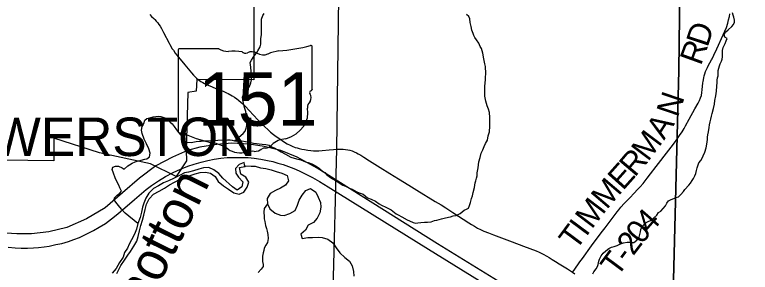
# Model space of a CAD drawing. Extents: x -19.9 to 41.9, y 0 to 32.3.
# Drawn here: x 6.268 to 8.077, y 16.956 to 17.59 of the extents above; entities that cross this region are included whole.
import ezdxf

# ---------------------------------------------------------------- set-up
doc = ezdxf.new("R2010")
doc.units = 0
for name, color, linetype in [('GM_X_Corporation', 7, 'Continuous'), ('GM_X_Corporation_Text', 7, 'Continuous'), ('GM_X_Major_River', 7, 'Continuous'), ('GM_X_Major_River_Text', 7, 'Continuous'), ('GM_X_Minor_River', 7, 'Continuous'), ('GM_X_Rail_Line', 7, 'Continuous'), ('GM_X_State_Location', 7, 'Continuous'), ('GM_X_State_Route', 7, 'Continuous'), ('GM_X_State_Shield', 7, 'Continuous'), ('GM_X_Township', 7, 'Continuous'), ('GM_X_Township_Road', 7, 'Continuous'), ('GM_X_Township_Road_Text', 7, 'Continuous')]:
    doc.layers.add(name, color=color, linetype=linetype)

msp = doc.modelspace()

# ---------------------------------------------------------------- linework, layer by layer
at = {"layer": 'GM_X_Corporation'}
for points in [[(2.1, 17.918), (2.1, 14.1), (7.8246, 14.1), (7.8518, 15.3043), (7.854, 15.4058), (7.8702, 16.1679), (7.8776, 16.5173), (7.9012, 17.4524), (7.9072, 17.9171)], [(6.8558, 17.6308), (6.8557, 17.4298), (6.7153, 17.4299), (6.7144, 17.4018), (6.6932, 17.3984), (6.6898, 17.2551), (6.6899, 17.2302), (6.6652, 17.1916), (6.6019, 17.2222), (6.4766, 17.2495), (6.3638, 17.2855), (6.3638, 17.2303), (5.8542, 17.2364), (5.8562, 17.5075), (6.2079, 17.7506)]]:
    msp.add_lwpolyline(points, dxfattribs=at)
msp.add_lwpolyline([(7.8246, 14.1), (8.9, 14.1), (8.9, 17.8974), (7.9072, 17.9171), (7.9012, 17.4524), (7.8776, 16.5173), (7.8702, 16.1679), (7.854, 15.4058), (7.8518, 15.3043)], close=True, dxfattribs=at)
at = {"layer": 'GM_X_Major_River'}
for points in [[(6.8336, 17.216), (6.8324, 17.2259), (6.8195, 17.2212), (6.8106, 17.2115), (6.8117, 17.2), (6.8184, 17.1897), (6.8291, 17.1784), (6.8263, 17.1658), (6.815, 17.1574), (6.8031, 17.1659), (6.7793, 17.1877), (6.7697, 17.1989), (6.7574, 17.2079), (6.7448, 17.2138), (6.7319, 17.2129), (6.7202, 17.2097), (6.7073, 17.2054), (6.6952, 17.2018), (6.6853, 17.2002), (6.6729, 17.194), (6.6601, 17.1874), (6.6457, 17.1804), (6.634, 17.1757), (6.6215, 17.1687), (6.6087, 17.1621), (6.5975, 17.1506), (6.5904, 17.1383), (6.5856, 17.1257), (6.5819, 17.1162), (6.5794, 17.1037), (6.5762, 17.0907), (6.5706, 17.0755), (6.5674, 17.0618), (6.5626, 17.0492), (6.5552, 17.0358), (6.5496, 17.0251), (6.5448, 17.0152), (6.5381, 17.0045), (6.5341, 16.9927), (6.5255, 16.9793), (6.5173, 16.9652), (6.5076, 16.9533)], [(6.5186, 16.9527), (6.5242, 16.9626), (6.5286, 16.9721), (6.5376, 16.9855), (6.5461, 16.9974), (6.5525, 17.007), (6.5607, 17.0196), (6.5678, 17.0322), (6.571, 17.044), (6.575, 17.0577), (6.5779, 17.0706), (6.5819, 17.0843), (6.5856, 17.0965), (6.5888, 17.1098), (6.5921, 17.1235), (6.5988, 17.1365), (6.6089, 17.1477), (6.6232, 17.155), (6.6361, 17.1624), (6.6481, 17.1705), (6.6606, 17.1771), (6.6745, 17.1849), (6.6862, 17.1903), (6.6991, 17.1939), (6.7119, 17.1982), (6.7237, 17.2014), (6.737, 17.202), (6.7491, 17.1998), (6.7606, 17.1912), (6.7684, 17.1788), (6.781, 17.1683), (6.7937, 17.1605), (6.8067, 17.1516), (6.8196, 17.1483), (6.831, 17.153), (6.8392, 17.1649), (6.8436, 17.1778), (6.8362, 17.1895), (6.8236, 17.1969), (6.8203, 17.2132)], [(6.8203, 17.2132), (6.8336, 17.216)], [(6.8336, 17.216), (6.8363, 17.2176), (6.8492, 17.217), (6.8594, 17.2167), (6.8724, 17.2127), (6.8857, 17.2113), (6.8987, 17.2077), (6.9105, 17.2037), (6.9246, 17.1993), (6.9376, 17.1938), (6.9415, 17.1805), (6.934, 17.1698), (6.9216, 17.1625), (6.9088, 17.1566), (6.8963, 17.1496), (6.8885, 17.137), (6.8898, 17.1245), (6.8956, 17.112), (6.9083, 17.1008), (6.9213, 17.096), (6.9308, 17.0954), (6.9444, 17.1005), (6.9576, 17.1079), (6.9631, 17.1208), (6.9671, 17.1334), (6.9746, 17.1456), (6.9836, 17.1567), (6.9957, 17.1615), (7.0083, 17.1525), (7.0141, 17.1404), (7.02, 17.1276), (7.0205, 17.1158), (7.018, 17.1021), (7.0113, 17.0892), (7.0024, 17.0784), (6.9895, 17.0718), (6.9832, 17.0592), (6.9712, 17.0496), (6.9747, 17.039), (6.9884, 17.0414), (7.0001, 17.0416), (7.0138, 17.0421), (7.0237, 17.0415), (7.0378, 17.0371), (7.0504, 17.0282), (7.0582, 17.0161), (7.0678, 17.0037), (7.0797, 16.9917), (7.0916, 16.9827), (7.0982, 16.9711), (7.1014, 16.9578), (7.1023, 16.9457)]]:
    msp.add_lwpolyline(points, dxfattribs=at)
at = {"layer": 'GM_X_Minor_River'}
for points in [[(6.8082, 17.2791), (6.8295, 17.297), (6.8344, 17.3031), (6.8369, 17.31), (6.8383, 17.3169), (6.8381, 17.3348), (6.8372, 17.3458), (6.8363, 17.3512), (6.8347, 17.3561), (6.8332, 17.3614), (6.8304, 17.372), (6.8287, 17.3811), (6.8282, 17.3868), (6.8304, 17.3922), (6.8338, 17.3972), (6.8416, 17.408), (6.8453, 17.413), (6.8486, 17.4218), (6.8504, 17.4298), (6.851, 17.4397), (6.8497, 17.45), (6.8484, 17.4607), (6.8476, 17.466), (6.8471, 17.4724), (6.8501, 17.4778), (6.8545, 17.484), (6.8575, 17.489), (6.8623, 17.4948), (6.866, 17.5009), (6.8715, 17.5105), (6.8734, 17.517), (6.8732, 17.5254), (6.8735, 17.5304), (6.8745, 17.541), (6.8744, 17.5468), (6.875, 17.5616), (6.8748, 17.5723), (6.8751, 17.5791), (6.8777, 17.5876), (6.881, 17.5929)], [(7.0412, 17.1912), (7.0496, 17.1853), (7.0606, 17.179), (7.0751, 17.1704), (7.0812, 17.1675), (7.0927, 17.1619), (7.0976, 17.1601), (7.1091, 17.1534), (7.1148, 17.1512), (7.1251, 17.1476), (7.1354, 17.139), (7.1442, 17.136), (7.1548, 17.1305), (7.1644, 17.1245), (7.1701, 17.1212), (7.1804, 17.116), (7.1934, 17.109), (7.206, 17.0993), (7.2113, 17.0971), (7.2201, 17.0919), (7.2327, 17.0848), (7.2392, 17.0826), (7.2476, 17.0782), (7.2537, 17.0768), (7.259, 17.0776), (7.2665, 17.0785), (7.276, 17.079), (7.2835, 17.0791), (7.2922, 17.08), (7.3005, 17.0828), (7.3062, 17.084), (7.3179, 17.0873), (7.3239, 17.0885), (7.3349, 17.0917), (7.3401, 17.0925), (7.3465, 17.0945), (7.3534, 17.095), (7.3582, 17.0978), (7.3635, 17.1005), (7.3732, 17.1087), (7.3789, 17.1114), (7.3838, 17.1134), (7.3867, 17.1203), (7.3889, 17.1272), (7.3917, 17.1375), (7.3935, 17.1436), (7.3953, 17.1524), (7.3986, 17.1643), (7.4007, 17.1761), (7.4017, 17.1811), (7.4035, 17.1872), (7.405, 17.1933), (7.4056, 17.2002), (7.4077, 17.2128), (7.4098, 17.2273), (7.4123, 17.238), (7.4151, 17.2491), (7.4192, 17.2567), (7.4225, 17.2656), (7.4262, 17.2725), (7.4306, 17.2805), (7.4323, 17.2912), (7.4356, 17.3012), (7.4362, 17.3153), (7.4364, 17.324), (7.4366, 17.337), (7.4353, 17.3492), (7.4329, 17.3575), (7.4302, 17.3651), (7.427, 17.3765), (7.4245, 17.3894), (7.4239, 17.4042), (7.4245, 17.4141), (7.4258, 17.4298), (7.4263, 17.4511), (7.4262, 17.4564), (7.4254, 17.4621), (7.4241, 17.469), (7.4221, 17.4811), (7.4192, 17.4948), (7.4157, 17.5069), (7.4129, 17.5118), (7.409, 17.5194), (7.4036, 17.5281), (7.3998, 17.5334), (7.397, 17.5383), (7.3958, 17.5432), (7.3923, 17.5519), (7.3903, 17.561), (7.3883, 17.5709), (7.387, 17.5793), (7.3846, 17.5849), (7.3793, 17.5902)], [(7.9685, 17.2617), (7.9706, 17.2708), (7.9716, 17.2823), (7.9719, 17.288), (7.973, 17.2937), (7.9744, 17.3017), (7.9761, 17.3124), (7.9771, 17.3185), (7.9786, 17.3262), (7.9804, 17.3327), (7.9818, 17.3399), (7.9832, 17.3464), (7.9864, 17.359), (7.9889, 17.3698), (7.9903, 17.3785), (7.992, 17.3896), (7.9938, 17.4018), (7.9947, 17.414), (7.9954, 17.4232), (7.9953, 17.4289), (7.9963, 17.4342), (7.9981, 17.4396), (7.9984, 17.4476), (7.9983, 17.4525), (7.9994, 17.4579), (8.0012, 17.4636), (8.0027, 17.4686), (8.006, 17.4755), (8.0078, 17.4805), (8.0089, 17.4862), (8.0086, 17.5015), (8.0108, 17.5087), (8.0152, 17.5191), (8.0178, 17.5256), (8.02, 17.531), (8.0146, 17.5347), (8.0126, 17.5404), (8.0163, 17.5465), (8.0231, 17.5527), (8.0317, 17.5605), (8.0361, 17.5655), (8.0383, 17.5712), (8.0383, 17.5762), (8.037, 17.5834), (8.0347, 17.5887), (8.0331, 17.5944)], [(6.5373, 17.2094), (6.5456, 17.2177), (6.5504, 17.2204), (6.5568, 17.2243), (6.564, 17.2275), (6.5693, 17.2291), (6.5787, 17.2319), (6.5874, 17.2339), (6.593, 17.2351), (6.5994, 17.2398), (6.6008, 17.249), (6.598, 17.2592), (6.5917, 17.2721), (6.5863, 17.283), (6.5815, 17.2974), (6.5799, 17.3054), (6.5813, 17.3146), (6.5854, 17.3219), (6.5879, 17.3299), (6.5927, 17.3342), (6.6026, 17.337), (6.6082, 17.3386), (6.6146, 17.3394), (6.6207, 17.3399), (6.6275, 17.3389), (6.637, 17.3356), (6.6431, 17.3319), (6.6504, 17.3255), (6.6554, 17.321), (6.6597, 17.3146), (6.6655, 17.3063), (6.6712, 17.2992), (6.6763, 17.2928), (6.6797, 17.2871), (6.6828, 17.2822), (6.6897, 17.2762), (6.7019, 17.2749), (6.7143, 17.2773), (6.7215, 17.2782), (6.7264, 17.2787), (6.7344, 17.2792), (6.7537, 17.2802), (6.7677, 17.2812), (6.7911, 17.2819), (6.7979, 17.2816), (6.8029, 17.281), (6.8082, 17.2791), (6.8143, 17.2788), (6.8195, 17.2797), (6.8267, 17.2794), (6.8355, 17.2773), (6.8488, 17.2748), (6.8548, 17.2737), (6.8768, 17.271), (6.8852, 17.27), (6.8935, 17.2686), (6.8996, 17.2645), (6.9061, 17.2623), (6.9153, 17.2571), (6.9233, 17.2523), (6.934, 17.246), (6.9473, 17.2393), (6.961, 17.2353), (6.9713, 17.2321), (6.9831, 17.2273), (6.9892, 17.2255), (6.9983, 17.2222), (7.009, 17.2166), (7.0178, 17.2107), (7.0247, 17.2043), (7.0308, 17.201), (7.035, 17.1961), (7.0412, 17.1912)], [(7.6897, 16.9516), (7.6927, 16.957), (7.6979, 16.9643), (7.7016, 16.9701), (7.703, 16.9751), (7.7044, 16.9831), (7.7059, 16.988), (7.7103, 16.9965), (7.7155, 17.003), (7.7218, 17.0081), (7.729, 17.0139), (7.7357, 17.0171), (7.7425, 17.0194), (7.7497, 17.0218), (7.7561, 17.0246), (7.7655, 17.0282), (7.7742, 17.0298), (7.7791, 17.0299), (7.7855, 17.0292), (7.7908, 17.0286), (7.7983, 17.0348), (7.8035, 17.0417), (7.8067, 17.0555), (7.8078, 17.0608), (7.8111, 17.0685), (7.8189, 17.0766), (7.8261, 17.0805), (7.8317, 17.0833), (7.8399, 17.0898), (7.847, 17.0964), (7.8515, 17.1026), (7.8575, 17.1057), (7.8631, 17.1123), (7.869, 17.1196), (7.872, 17.1258), (7.8757, 17.1319), (7.8825, 17.1351), (7.8892, 17.1374), (7.8945, 17.1398), (7.9002, 17.1414), (7.9065, 17.1472), (7.9129, 17.1542), (7.9158, 17.1592), (7.9263, 17.17), (7.9303, 17.1754), (7.9344, 17.1815), (7.9378, 17.1865), (7.9411, 17.1927), (7.9429, 17.1984), (7.945, 17.2065), (7.9465, 17.213), (7.9479, 17.2179), (7.9508, 17.2248), (7.9553, 17.2306), (7.9586, 17.2367), (7.9612, 17.2425), (7.9656, 17.2513), (7.9685, 17.2617)], [(6.5706, 17.0755), (6.5393, 17.1014), (6.5304, 17.1112), (6.5227, 17.1198), (6.5166, 17.1285), (6.5127, 17.1338), (6.513, 17.1391), (6.5197, 17.1457), (6.5265, 17.1504), (6.5305, 17.1557), (6.5266, 17.1637), (6.5235, 17.1697), (6.5189, 17.1792), (6.5149, 17.1883), (6.511, 17.1996), (6.5078, 17.2087), (6.5093, 17.2145), (6.5153, 17.2172), (6.5232, 17.217), (6.5316, 17.2125), (6.5372, 17.2095)], [(6.8898, 17.1245), (6.8814, 17.1127), (6.8807, 17.1039), (6.8813, 17.0932), (6.8814, 17.0871), (6.8826, 17.0803), (6.885, 17.0708), (6.887, 17.0632), (6.889, 17.0572), (6.8902, 17.0484), (6.8908, 17.0385), (6.8894, 17.0286), (6.8853, 17.0221), (6.8816, 17.0152), (6.8802, 17.0091), (6.8788, 17.0033), (6.877, 16.9953), (6.8771, 16.99), (6.8776, 16.9824), (6.8788, 16.9751), (6.8792, 16.9702), (6.874, 16.9629), (6.8662, 16.9552)]]:
    msp.add_lwpolyline(points, dxfattribs=at)
at = {"layer": 'GM_X_Rail_Line'}
for points in [[(7.5103, 16.9007), (7.3078, 17.0259), (7.0117, 17.2117), (6.9625, 17.2392), (6.9227, 17.2551), (6.8813, 17.2656), (6.8446, 17.2711), (6.8016, 17.2731), (6.7651, 17.2702), (6.7231, 17.2636), (6.6928, 17.2552), (6.6556, 17.2394), (6.6145, 17.2176), (6.575, 17.187), (6.5327, 17.1509), (6.4901, 17.114), (6.444, 17.0875), (6.3956, 17.066), (6.3512, 17.0553), (6.309, 17.0505), (6.2726, 17.0501), (6.2324, 17.0527)], [(6.2512, 17.0173), (6.2687, 17.0158), (6.2832, 17.0151), (6.2995, 17.0149), (6.3136, 17.0158), (6.3262, 17.0167), (6.3404, 17.0181), (6.3523, 17.02), (6.369, 17.0236), (6.3833, 17.0267), (6.4, 17.0318), (6.4135, 17.0363), (6.4269, 17.0416), (6.445, 17.05), (6.4613, 17.0581), (6.4757, 17.0666), (6.4907, 17.076), (6.5055, 17.087), (6.5214, 17.0997), (6.5622, 17.1349), (6.5914, 17.1596), (6.6045, 17.1693), (6.6211, 17.1806), (6.6388, 17.1914), (6.6572, 17.2016), (6.6754, 17.2095), (6.6938, 17.217), (6.7091, 17.2221), (6.7263, 17.227), (6.7425, 17.231), (6.7586, 17.2342), (6.7744, 17.2363), (6.7903, 17.2378), (6.8067, 17.2384), (6.8242, 17.2386), (6.8418, 17.2379), (6.8564, 17.2367), (6.8734, 17.2343), (6.8894, 17.2311), (6.9029, 17.2281), (6.9153, 17.2246), (6.9278, 17.2211), (6.9411, 17.2163), (6.9541, 17.2111), (6.9675, 17.2054), (6.9824, 17.1981), (7.0001, 17.1887), (7.0174, 17.1788), (7.0386, 17.1661), (7.2854, 17.0128), (7.5349, 16.858)]]:
    msp.add_lwpolyline(points, dxfattribs=at)
at = {"layer": 'GM_X_State_Route'}
for points in [[(6.5997, 17.5899), (6.6044, 17.5857), (6.6098, 17.5805), (6.6122, 17.578), (6.6156, 17.5742), (6.6195, 17.5695), (6.6221, 17.5659), (6.6251, 17.5612), (6.6285, 17.5554), (6.6334, 17.5462), (6.6473, 17.5193), (6.6489, 17.5165), (6.6553, 17.506), (6.6579, 17.5021), (6.6627, 17.4951), (6.6663, 17.4905), (6.6861, 17.4666), (6.7028, 17.4468), (6.7077, 17.4411), (6.7123, 17.4362), (6.715, 17.4336), (6.7189, 17.4303), (6.7223, 17.4278), (6.7255, 17.4257), (6.7302, 17.4228), (6.7349, 17.4203), (6.7392, 17.4183), (6.7536, 17.4121), (6.7627, 17.4084), (6.7803, 17.4012), (6.7889, 17.3974), (6.7925, 17.3956), (6.8023, 17.3903), (6.8081, 17.3868), (6.8138, 17.383), (6.8183, 17.3796), (6.8251, 17.3739), (6.8292, 17.3701), (6.8352, 17.3641), (6.8443, 17.3542), (6.8657, 17.3312), (6.87, 17.3267), (6.8832, 17.3136), (6.89, 17.3073), (6.8972, 17.3008), (6.9044, 17.2947), (6.9072, 17.2926), (6.9228, 17.2814), (6.9252, 17.2797), (6.9341, 17.2743), (6.9382, 17.272), (6.9451, 17.2684), (6.9501, 17.2661), (6.9575, 17.2632), (6.9626, 17.2616), (6.9677, 17.2602), (6.9738, 17.2588), (6.9806, 17.2575), (6.9888, 17.2562), (6.996, 17.2553), (7.0023, 17.2549), (7.0095, 17.2547), (7.016, 17.2548), (7.0243, 17.2552), (7.0414, 17.2568), (7.0516, 17.2579), (7.0583, 17.2586), (7.0655, 17.259)], [(7.0655, 17.259), (7.076, 17.2588), (7.0814, 17.2582), (7.0873, 17.2571), (7.0918, 17.256), (7.098, 17.2542), (7.1029, 17.2522), (7.1082, 17.2499), (7.1129, 17.2474), (7.119, 17.2437), (7.1269, 17.2388), (7.1403, 17.2302), (7.1665, 17.2138), (7.1907, 17.1988), (7.2115, 17.186), (7.2371, 17.1701), (7.2566, 17.1579), (7.3023, 17.1299), (7.317, 17.1213), (7.3281, 17.1143), (7.3457, 17.1028), (7.3846, 17.0774), (7.3911, 17.0736), (7.3989, 17.0688), (7.4064, 17.0646), (7.4137, 17.0609), (7.4218, 17.0572), (7.4331, 17.0525), (7.4452, 17.0477), (7.4916, 17.0303), (7.5195, 17.0199), (7.5502, 17.0087), (7.5579, 17.0054), (7.5626, 17.003), (7.5676, 17.0005), (7.5764, 16.9952), (7.5822, 16.9917), (7.5896, 16.9873), (7.5978, 16.9823), (7.6074, 16.9763), (7.6273, 16.9637), (7.6402, 16.9558), (7.6458, 16.9521)]]:
    msp.add_lwpolyline(points, dxfattribs=at)
at = {"layer": 'GM_X_State_Shield'}
for p, q in [((6.6699, 17.5023), (6.6699, 17.3022)), ((6.7697, 17.5058), (6.6732, 17.5058)), ((6.9995, 17.406), (6.9995, 17.5107)), ((6.9995, 17.4061), (6.9995, 17.406))]:
    msp.add_line(p, q, dxfattribs=at)
for centre, major_axis, start_param, end_param in [((6.6737, 17.5028), (0.00382, 0), 1.712693, 3.28349), ((6.7927, 17.529), (0.037, 0), 4.042523, 4.731795), ((6.805, 17.3934), (0.133, 0), 1.404758, 1.657858), ((6.8351, 17.5038), (0.0107, 0), 3.836095, 5.185415), ((6.8508, 17.4807), (0.0222, 0), 0.950623, 2.079405), ((6.9267, 17.4446), (0.0703, 0), 1.699011, 2.107814), ((6.8821, 17.7786), (0.3495, 0), 4.814394, 5.042369), ((6.9959, 17.5112), (0.00367, 0), 6.141152, 7.989035), ((6.8795, 17.5124), (0.0267, 0), 4.081561, 5.145723), ((6.9987, 17.3984), (0.00568, 0), 1.883978, 3.671073), ((6.9625, 17.3851), (0.0341, 0), 5.934695, 6.695948), ((6.9956, 17.4056), (0.00393, 0), 5.05454, 6.418171), ((7.0127, 17.3622), (0.0248, 0), 2.387724, 3.262537), ((6.9017, 17.3489), (0.0874, 0), 5.101752, 6.440018), ((6.6737, 17.3018), (0.00385, 0), 3.00124, 4.508301), ((6.6743, 17.3222), (0.0294, 0), 4.665946, 4.897461), ((6.6803, 17.2907), (0.0106, 0), 0.519207, 1.627899), ((6.8142, 17.4705), (0.2524, 0), 4.195997, 4.488961), ((6.9386, 17.246), (0.0479, 0), 1.647645, 2.488434), ((6.7389, 17.2123), (0.079, 0), 0.823519, 1.323587), ((6.8779, 17.2828), (0.0282, 0), 4.937069, 5.64225), ((6.8243, 17.2897), (0.0501, 0), 4.026481, 4.996735), ((6.8533, 17.2205), (0.0412, 0), 1.495662, 1.94098), ((6.8569, 17.2747), (0.0267, 0), 4.691044, 5.507374), ((6.8811, 17.2553), (0.00752, 0), 1.147584, 2.315152)]:
    msp.add_ellipse(centre, major_axis=major_axis, ratio=0.8, start_param=start_param, end_param=end_param, dxfattribs=at)
at = {"layer": 'GM_X_Township'}
for p, q in [((7.0652, 17.7237), (7.0592, 17.259)), ((7.0592, 17.259), (7.0356, 16.3239))]:
    msp.add_line(p, q, dxfattribs=at)
at = {"layer": 'GM_X_Township_Road'}
msp.add_lwpolyline([(7.6402, 16.9558), (7.6439, 16.9609), (7.6579, 16.9813), (7.6642, 16.9899), (7.6865, 17.0206), (7.7105, 17.0527), (7.7198, 17.0652), (7.7297, 17.0782), (7.7395, 17.0909), (7.7499, 17.1046), (7.7535, 17.109), (7.7591, 17.1156), (7.7672, 17.1247), (7.7807, 17.1388), (7.7917, 17.1502), (7.8001, 17.1595), (7.8065, 17.1663), (7.8133, 17.1745), (7.8187, 17.181), (7.8238, 17.1877), (7.8318, 17.198), (7.8455, 17.2158), (7.8771, 17.2562), (7.8829, 17.2638), (7.8904, 17.274), (7.8964, 17.2824), (7.9033, 17.2926), (7.9093, 17.3017), (7.9142, 17.3096), (7.9178, 17.3159), (7.9268, 17.3327), (7.9406, 17.358), (7.9486, 17.3719), (7.9525, 17.3789), (7.9548, 17.3847), (7.9569, 17.3908), (7.9582, 17.3982), (7.959, 17.4044), (7.9604, 17.4223), (7.9609, 17.4255), (7.9629, 17.4347), (7.9639, 17.439), (7.9651, 17.4442), (7.9668, 17.4496), (7.9694, 17.4551), (7.9716, 17.4596), (7.9737, 17.4635), (7.9821, 17.4785), (7.9834, 17.4812), (7.9875, 17.4904), (7.9947, 17.5056), (8.0104, 17.5399), (8.0148, 17.549), (8.0185, 17.5586), (8.0217, 17.5686), (8.0238, 17.5771), (8.0257, 17.5857), (8.0269, 17.5915)], dxfattribs=at)

# ---------------------------------------------------------------- texts
at = {"layer": 'GM_X_Corporation_Text'}
msp.add_text('BOWERSTON', height=0.0947, rotation=0, dxfattribs=at).set_placement((6.0295, 17.2418))
at = {"layer": 'GM_X_Major_River_Text'}
msp.add_text('Conotton', height=0.09472, rotation=63.5646, dxfattribs=at).set_placement((6.5202, 16.7172))
at = {"layer": 'GM_X_State_Location'}
msp.add_text('151', height=0.000189, rotation=0, dxfattribs=at).set_placement((6.7642, 17.3752))
for s in ['s', 'r']:
    msp.add_text(s, height=0.000189, dxfattribs=at).set_placement((6.831, 17.389))
at = {"layer": 'GM_X_State_Shield'}
msp.add_text('151', height=0.13184, dxfattribs=at).set_placement((6.7185, 17.3163))
at = {"layer": 'GM_X_Township_Road_Text'}
for s, rotation, p in [('D', 71.7234, (7.9719, 17.5079)), ('R', 70.1097, (7.9556, 17.4627)), ('N', 71.1616, (7.8987, 17.335)), ('A', 57.1902, (7.865, 17.2794)), ('M', 53.1348, (7.8255, 17.2265)), ('R', 49.7413, (7.7931, 17.188)), ('E', 48.323, (7.7638, 17.1551)), ('M', 49.5663, (7.724, 17.1084)), ('M', 52.7048, (7.6872, 17.06)), ('4', 48.7264, (7.8316, 17.049)), ('I', 53.4205, (7.6734, 17.0414)), ('0', 51.3792, (7.8102, 17.0222)), ('T', 53.4215, (7.648, 17.0073)), ('2', 52.6545, (7.7892, 16.9946)), ('T', 53.4215, (7.75, 16.942)), ('-', 53.2409, (7.7753, 16.9761))]:
    msp.add_text(s, height=0.0568, rotation=rotation, dxfattribs=at).set_placement(p)

doc.saveas('drawing.dxf')
